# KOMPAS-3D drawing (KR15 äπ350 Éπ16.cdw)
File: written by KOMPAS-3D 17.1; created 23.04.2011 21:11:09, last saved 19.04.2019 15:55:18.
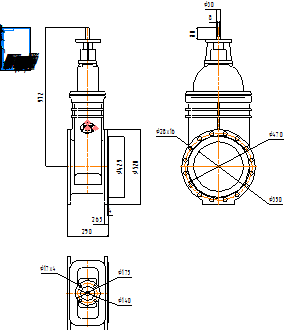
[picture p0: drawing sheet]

Sheet 1: A4, portrait

Title block, sheet 1: name: KR15 Ду350 Ру16; material: Внимание! Данный продукт является объектом авторского права ООО «Торговый Дом АДЛ». / Запрещается изменение, копирование, распространение / (в том числе путем копирования на другие сайты и ресурсы в Интернете) / или любое иное использование информации и объектов без предварительного / согласия правообладателя (ООО «Торговый Дом АДЛ»).; scale: 1:1; sheets: 1; organisation: ООО "Торговый дом АДЛ"; sheet format: A4; stored path: \\adlc.lan\data\АДЛ_ПКД\3D-модели\ADL production\Клиновые задвижки серии KR ГРАНАР\Клиновые задвижки KR15\С голым штоком\KOMPAS 2D\KR15 Ду350 Ру16.cdw

Views: Спереди 4, Проекционный вид 5
Dimensions and other numbers on the sheet: 290; 26,5; 4; 972; 429; 520; 175; 17; 140; 1:1; 1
